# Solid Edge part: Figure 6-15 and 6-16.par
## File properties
Author: Ashutosh-CADCIM
Template: Iso Metric Part.par
Last saved by: Ashutosh-CADCIM
Revision: 2
Application: Solid Edge
Accuracy: 0.990
Username: Ashutosh-CADCIM
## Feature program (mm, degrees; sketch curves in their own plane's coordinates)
sketch for "unnamed Hole 1" plane through (0, 0, 35.6467) normal (0, 0, 1) x-axis (1, 0, 0)
  hole centre (-29.3702, -9.6019) bore radius 5
hole "unnamed Hole 1" through
sketch for "unnamed Hole 2" plane through (0, 0, 35.6467) normal (0, 0, 1) x-axis (1, 0, 0)
  hole centre (1.0428, 6.1255) bore radius 5
hole "unnamed Hole 2" through
pattern "unnamed Pattern 1" of "unnamed Hole 1", "unnamed Hole 2"
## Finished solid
Body 1: solid body, 12 faces, 28 edges, 16 vertices.
  Faces by surface: cylinder 6, plane 6
  Edges by curve: line 16, circle 12
Bounding box of the edges (mm): 100.000 x 60.000 x 10.000, from (-50, -30, 25.6467) to (50, 30, 35.6467).
Cylindrical faces by radius (mm): R5 x2, R15 x4
Planar faces by outward normal: +x 1, +y 1, +z 1, -x 1, -y 1, -z 1
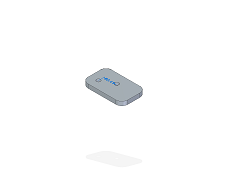
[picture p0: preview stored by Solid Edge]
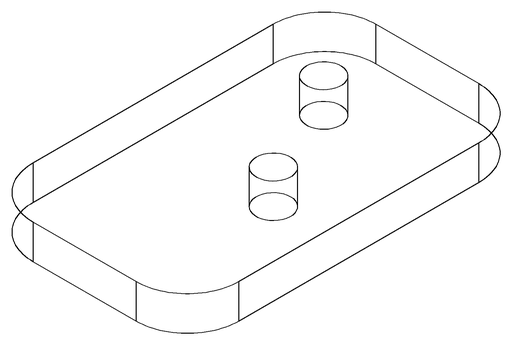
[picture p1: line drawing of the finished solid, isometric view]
